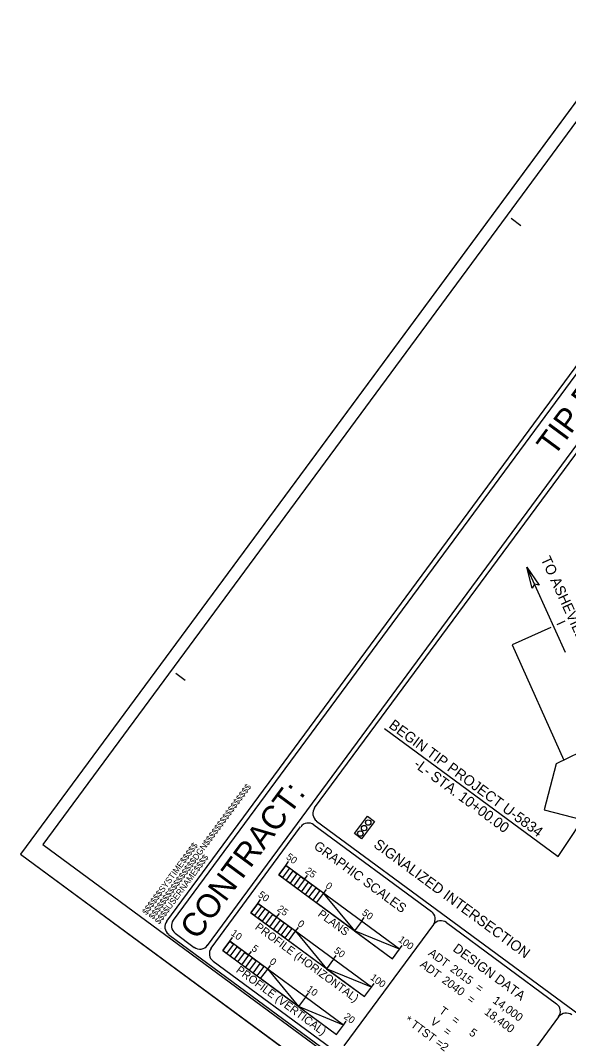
# Model space of a CAD drawing. Extents: x 945666 to 965748, y 644452 to 663300.
# Drawn here: x 945666 to 951483, y 652491 to 663300 of the extents above; entities that cross this region are included whole.
import ezdxf

# ---------------------------------------------------------------- set-up
doc = ezdxf.new("R2010")
doc.units = 0
for name, color, linetype in [('Old_Level_23', 7, 'Continuous'), ('Prop PHM Traffic Signal CELL', 7, 'Continuous'), ('Prop Terminator CELL', 7, 'Continuous'), ('Sheet Cutting Line CELL', 7, 'Continuous'), ('Sheet Data Field CELL', 7, 'Continuous'), ('Sheet Plan Layout CELL', 7, 'Continuous'), ('Sheet Plot Border Inside CELL', 7, 'Continuous'), ('Sheet Plot Border Outside CELL', 7, 'Continuous'), ('Sheet Title CELL', 7, 'Continuous')]:
    doc.layers.add(name, color=color, linetype=linetype)

msp = doc.modelspace()

# ---------------------------------------------------------------- linework, layer by layer
at = {"layer": 'Old_Level_23'}
for p, q in [((951450, 656591), (951039, 657494)), ((949531, 655784), (951372, 654425)), ((951372, 654425), (952015, 655396))]:
    msp.add_line(p, q, dxfattribs=at)
at = {"layer": 'Prop PHM Traffic Signal CELL'}
for p, q in [((949212, 654667), (949348, 654851)), ((949348, 654851), (949422, 654796)), ((949422, 654796), (949286, 654612)), ((949286, 654612), (949212, 654667))]:
    msp.add_line(p, q, dxfattribs=at)
for centre in [(949313, 654726), (949357, 654785), (949273, 654668)]:
    msp.add_circle(centre, 28.8, dxfattribs=at)
at = {"layer": 'Prop Terminator CELL'}
msp.add_lwpolyline([(951097, 657273), (951039, 657494), (951169, 657305), (951121, 657314)], close=True, dxfattribs=at)
at = {"layer": 'Sheet Cutting Line CELL'}
for p, q in [((952195, 663300), (945666, 654448)), ((945666, 654448), (959219, 644452))]:
    msp.add_line(p, q, dxfattribs=at)
at = {"layer": 'Sheet Data Field CELL'}
for p, q in [((948481, 654330), (948511, 654370)), ((948682, 654182), (948712, 654222)), ((949286, 653736), (949315, 653777)), ((947159, 653657), (947159, 653657)), ((949688, 653440), (949718, 653480))]:
    msp.add_line(p, q, dxfattribs=at)
at = {"layer": 'Sheet Plan Layout CELL'}
for p, q in [((951296, 656855), (950883, 656670)), ((950883, 656670), (951431, 655446)), ((952376, 655905), (951350, 655407)), ((951350, 655407), (951225, 654918)), ((951225, 654918), (952432, 654609))]:
    msp.add_line(p, q, dxfattribs=at)
msp.add_lwpolyline([(951443, 656921), (951358, 656883)], dxfattribs=at)
at = {"layer": 'Sheet Plot Border Inside CELL'}
msp.add_lwpolyline([(945904, 654551), (959316, 644660), (965578, 653151), (952166, 663042)], close=True, dxfattribs=at)
at = {"layer": 'Sheet Plot Border Outside CELL'}
msp.add_lwpolyline([(965748, 653305), (952195, 663300), (945666, 654448), (959219, 644452)], close=True, dxfattribs=at)
at = {"layer": 'Sheet Title CELL'}
for p, q in [((947650, 653481), (953704, 661690)), ((948788, 654941), (953744, 661661)), ((950875, 661199), (950975, 661124)), ((950875, 661199), (950975, 661124)), ((947314, 656370), (947414, 656296)), ((947314, 656370), (947414, 656296)), ((947690, 653452), (948640, 654739)), ((948780, 654761), (950027, 653841)), ((948809, 654801), (960237, 646372)), ((948481, 654330), (948407, 654229)), ((948481, 654330), (948510, 654370)), ((948481, 654330), (948481, 654330)), ((949688, 653440), (948481, 654330)), ((948510, 654370), (948510, 654370)), ((948407, 654229), (949614, 653339)), ((948682, 654181), (948712, 654222)), ((948762, 654122), (948688, 654022)), ((948883, 654033), (948913, 654073)), ((948184, 653927), (948214, 653968)), ((948184, 653927), (948214, 653968)), ((948214, 653968), (948214, 653968)), ((948184, 653927), (948110, 653827)), ((948184, 653927), (948184, 653927)), ((949391, 653037), (948184, 653927)), ((948184, 653927), (948184, 653927)), ((949391, 653037), (948184, 653927)), ((948110, 653827), (949317, 652937)), ((948385, 653779), (948415, 653819)), ((948385, 653779), (948415, 653819)), ((949286, 653736), (949315, 653777)), ((947158, 653658), (947158, 653658)), ((947158, 653658), (947158, 653658)), ((947158, 653658), (947158, 653658)), ((947158, 653658), (947158, 653658)), ((948466, 653720), (948391, 653619)), ((948586, 653631), (948616, 653671)), ((948586, 653631), (948616, 653671)), ((950048, 653701), (949098, 652413)), ((949286, 653736), (949211, 653636)), ((950188, 653722), (951355, 652861)), ((947887, 653525), (947917, 653565)), ((947887, 653525), (947917, 653565)), ((947887, 653525), (947917, 653565)), ((947917, 653565), (947917, 653565)), ((947887, 653525), (947813, 653425)), ((947813, 653425), (949020, 652534)), ((947887, 653525), (947887, 653525)), ((949094, 652635), (947887, 653525)), ((947887, 653525), (947887, 653525)), ((949094, 652635), (947887, 653525)), ((947887, 653525), (947887, 653525)), ((949094, 652635), (947887, 653525)), ((949614, 653339), (949688, 653440)), ((949688, 653440), (949718, 653480)), ((948088, 653377), (948118, 653417)), ((948088, 653377), (948118, 653417)), ((948088, 653377), (948118, 653417)), ((948169, 653317), (948095, 653217)), ((948989, 653334), (948915, 653233)), ((948989, 653334), (949018, 653374)), ((948989, 653334), (949018, 653374)), ((948290, 653228), (948319, 653268)), ((948290, 653228), (948319, 653268)), ((948290, 653228), (948319, 653268)), ((949317, 652937), (949391, 653037)), ((949391, 653037), (949421, 653077)), ((949391, 653037), (949421, 653077)), ((948692, 652932), (948618, 652831)), ((948692, 652932), (948722, 652972)), ((948692, 652932), (948722, 652972)), ((948692, 652932), (948722, 652972)), ((949094, 652635), (949124, 652675)), ((949094, 652635), (949124, 652675)), ((949094, 652635), (949124, 652675)), ((951376, 652721), (950426, 651434)), ((949020, 652534), (949094, 652635))]:
    msp.add_line(p, q, dxfattribs=at)
for points in [[(953331, 662027), (947218, 653738)], [(953331, 662027), (947218, 653738)], [(953342, 661957), (947288, 653749)], [(947239, 653598), (959150, 644814)], [(947309, 653609), (947510, 653460)], [(947711, 653312), (948959, 652392)]]:
    msp.add_lwpolyline(points, dxfattribs=at)
for points in [[(948481, 654330), (948521, 654300), (948447, 654200), (948407, 654229)], [(948561, 654271), (948601, 654241), (948527, 654140), (948487, 654170)], [(948642, 654211), (948682, 654181), (948608, 654081), (948567, 654111)], [(948722, 654152), (948762, 654122), (948688, 654022), (948648, 654051)], [(948803, 654093), (948843, 654063), (948769, 653962), (948728, 653992)], [(948883, 654033), (949211, 653636), (948809, 653933)], [(948184, 653927), (948224, 653898), (948150, 653797), (948110, 653827)], [(948264, 653868), (948305, 653839), (948231, 653738), (948190, 653768)], [(948345, 653809), (948385, 653779), (948311, 653679), (948271, 653708)], [(948425, 653749), (948466, 653720), (948391, 653619), (948351, 653649)], [(948506, 653690), (948546, 653660), (948472, 653560), (948432, 653590)], [(948586, 653631), (948915, 653233), (948512, 653530)], [(949688, 653440), (949211, 653636), (949614, 653339)], [(947887, 653525), (947927, 653495), (947853, 653395), (947813, 653425)], [(947968, 653466), (948008, 653436), (947934, 653336), (947893, 653365)], [(948048, 653406), (948088, 653377), (948014, 653276), (947974, 653306)], [(948129, 653347), (948169, 653317), (948095, 653217), (948054, 653247)], [(948209, 653288), (948249, 653258), (948175, 653157), (948135, 653187)], [(948290, 653228), (948618, 652831), (948215, 653128)], [(949391, 653037), (948915, 653233), (949317, 652937)], [(949094, 652635), (948618, 652831), (949020, 652534)]]:
    msp.add_lwpolyline(points, close=True, dxfattribs=at)
for centre, start, end in [((948869, 654882), 143.5908, 233.5908), ((948721, 654680), 53.5908, 143.5908), ((947369, 653690), 143.5908, 233.5908), ((949968, 653760), 323.5908, 53.5908), ((947299, 653679), 143.5908, 233.5908), ((950129, 653642), 53.5908, 143.5908), ((947570, 653541), 233.5908, 323.5908), ((947771, 653393), 143.5908, 233.5908), ((951296, 652781), 323.5908, 53.5908), ((951457, 652662), 53.5908, 143.5908)]:
    msp.add_arc(centre, 100, start, end, dxfattribs=at)

# ---------------------------------------------------------------- texts
at = {"layer": 'Old_Level_23'}
for s, rotation, p in [('TO ASHEVILLE', 294.4374, (951185, 657582)), ('BEGIN TIP PROJECT U-5834', 323.5908, (949567, 655799)), ('-L- STA. 10+00.00 ', 323.5908, (949830, 655384)), ('SIGNALIZED INTERSECTION', 323.5908, (949405, 654531))]:
    msp.add_text(s, height=110, rotation=rotation, dxfattribs=at).set_placement(p)
at = {"layer": 'Sheet Data Field CELL'}
for s, height, p in [('50', 75, (948479, 654406)), ('25', 75, (948681, 654257)), ('50', 75, (948182, 654004)), ('25', 75, (948384, 653854)), ('50', 75, (949284, 653812)), ('10', 75, (947893, 653596)), ('100', 75, (949669, 653528)), ('5', 75, (948112, 653434)), ('50', 75, (948987, 653410)), ('ADT', 87.5, (949987, 653383)), ('ADT', 87.5, (949898, 653263)), ('2015', 87.5, (950219, 653214)), ('100', 75, (949373, 653126)), ('2040', 87.5, (950132, 653093)), ('10', 75, (948697, 653002)), ('=', 87.5, (950486, 653016)), ('=', 87.5, (950397, 652895)), ('14,000', 87.5, (950670, 652879)), ('T', 87.5, (950102, 652770)), ('18,400', 87.5, (950581, 652758)), ('20', 75, (949092, 652711)), ('* TTST =2', 87.5, (949737, 652669)), ('V', 87.5, (950008, 652654)), ('=', 87.5, (950234, 652675)), ('=', 87.5, (950145, 652554)), ('5', 87.5, (950419, 652538))]:
    msp.add_text(s, height=height, rotation=323.5908, dxfattribs=at).set_placement(p)
at = {"layer": 'Sheet Title CELL'}
for s, height, rotation, p in [('TIP PROJECT:', 250, 53.5908, (951328, 658660)), ('$$$$$$$$$$$$$$$$DGN$$$$$$$$$$$$$$$$', 65.62, 53.5908, (947075, 653750)), ('CONTRACT:', 250, 53.5908, (947543, 653529)), ('$$$$$$SYSTIME$$$$$', 65.62, 53.5908, (947005, 653799)), ('GRAPHIC SCALES', 100, 323.5908, (948771, 654516)), ('$$$$USERNAME$$$$', 65.62, 53.5908, (947140, 653700)), ('0', 75, 323.5908, (948897, 654099)), ('PLANS', 85, 323.5908, (948815, 653798)), ('0', 75, 323.5908, (948601, 653697)), ('PROFILE (HORIZONTAL)', 85, 323.5908, (948149, 653660)), ('0', 75, 323.5908, (948600, 653695)), ('DESIGN DATA', 100, 323.5908, (950247, 653428)), ('0', 75, 323.5908, (948303, 653293)), ('0', 75, 323.5908, (948303, 653293)), ('0', 75, 323.5908, (948304, 653294)), ('PROFILE (VERTICAL)', 85, 323.5908, (947947, 653203))]:
    msp.add_text(s, height=height, rotation=rotation, dxfattribs=at).set_placement(p)

doc.saveas('drawing.dxf')
